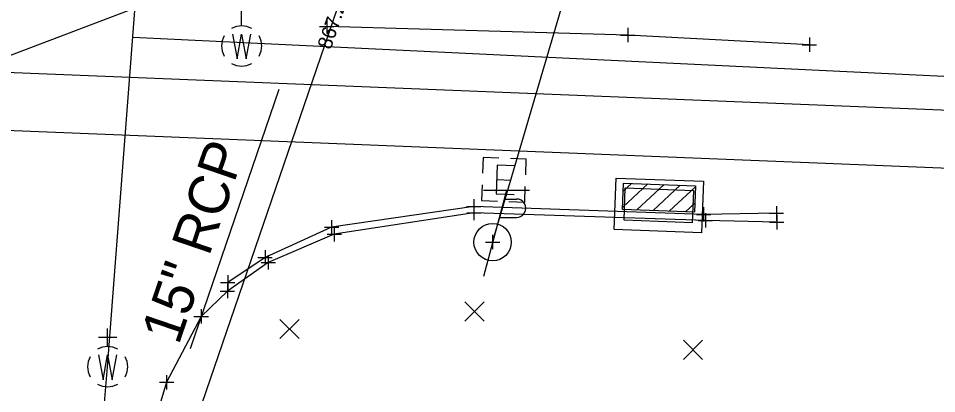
# Model space of a CAD drawing. Extents: x 1380440 to 1381945, y 468756 to 470369.
# Drawn here: x 1381624.1 to 1381687.9, y 470207.8 to 470234 of the extents above; entities that cross this region are included whole.
import ezdxf

# ---------------------------------------------------------------- set-up
doc = ezdxf.new("R2010")
doc.units = 0
for name, color, linetype in [('Animation Elements', 7, 'Continuous'), ('DR_X_Cells', 7, 'Continuous'), ('GE_P_Driveway_CL', 7, 'Continuous'), ('PM_X_Cells', 7, 'Continuous'), ('PV_P_Curb_Ramp', 7, 'Continuous'), ('PV_P_Joint', 7, 'Continuous'), ('PV_X_COP', 7, 'Continuous'), ('RW_P_Const_Limits', 7, 'Continuous'), ('RW_P_Esmt_TMP', 7, 'Continuous'), ('RW_X_CL', 7, 'Continuous'), ('SC_Scratch1', 7, 'Continuous'), ('SC_Shading1', 7, 'Continuous'), ('SH_Named_Boundary', 7, 'Continuous'), ('UT_X_Gas', 7, 'Continuous'), ('UT_X_Overhead_Combined', 7, 'Continuous'), ('UT_X_Sanitary_Line', 7, 'Continuous'), ('UT_X_Water', 7, 'Continuous'), ('X-CL', 7, 'Continuous')]:
    doc.layers.add(name, color=color, linetype=linetype)

msp = doc.modelspace()

# ---------------------------------------------------------------- linework, layer by layer
at = {"layer": 'Animation Elements'}
msp.add_lwpolyline([(1381657.035, 470218.369), (1381665.562, 470247.404)], dxfattribs=at)
at = {"layer": 'DR_X_Cells'}
msp.add_lwpolyline([(1381676.791, 470219.75), (1381671.827, 470219.886), (1381655.739, 470220.402), (1381646.018, 470218.916), (1381641.43, 470216.955), (1381638.594, 470214.962)], dxfattribs=at)
at = {"layer": 'GE_P_Driveway_CL'}
for p, q in [((1381655.103, 470212.868), (1381656.437, 470214.204)), ((1381655.103, 470214.204), (1381656.437, 470212.868)), ((1381642.237, 470211.656), (1381643.571, 470212.991)), ((1381642.237, 470212.991), (1381643.571, 470211.656)), ((1381670.301, 470210.201), (1381671.635, 470211.536)), ((1381670.301, 470211.536), (1381671.635, 470210.201))]:
    msp.add_line(p, q, dxfattribs=at)
at = {"layer": 'PM_X_Cells'}
for p, q in [((1381657.322, 470222.728), (1381658.322, 470222.691)), ((1381657.822, 470222.71), (1381657.822, 470222.71))]:
    msp.add_line(p, q, dxfattribs=at)
for points in [[(1381657.478, 470224.224), (1381656.378, 470224.264), (1381656.338, 470223.165)], [(1381659.336, 470223.054), (1381659.376, 470224.154), (1381658.277, 470224.194)], [(1381658.608, 470223.682), (1381657.359, 470223.728), (1381657.285, 470221.729), (1381658.535, 470221.683)], [(1381656.308, 470222.366), (1381656.268, 470221.266), (1381657.367, 470221.226)], [(1381658.166, 470221.196), (1381659.266, 470221.156), (1381659.306, 470222.255)]]:
    msp.add_lwpolyline(points, dxfattribs=at)
at = {"layer": 'PV_P_Curb_Ramp'}
for p, q in [((1381668.655, 470222.722), (1381668.655, 470222.722)), ((1381668.63, 470222.056), (1381668.63, 470222.056)), ((1381666.215, 470221.02), (1381666.215, 470221.02)), ((1381668.574, 470220.557), (1381668.574, 470220.557)), ((1381668.574, 470220.557), (1381668.574, 470220.557)), ((1381668.588, 470220.932), (1381668.588, 470220.932)), ((1381670.961, 470220.843), (1381670.961, 470220.843)), ((1381668.546, 470219.808), (1381668.546, 470219.808)), ((1381668.521, 470219.141), (1381668.521, 470219.141))]:
    msp.add_line(p, q, dxfattribs=at)
at = {"layer": 'PV_P_Joint'}
for p, q in [((1381667.828, 470222.419), (1381666.081, 470220.794)), ((1381666.699, 470222.461), (1381666.123, 470221.926)), ((1381668.957, 470222.377), (1381667.061, 470220.613)), ((1381670.086, 470222.335), (1381668.19, 470220.571)), ((1381671.138, 470222.222), (1381669.319, 470220.529)), ((1381671.096, 470221.089), (1381670.449, 470220.487))]:
    msp.add_line(p, q, dxfattribs=at)
for points in [[(1381671.561, 470219.027), (1381665.482, 470219.254), (1381665.615, 470222.835), (1381671.694, 470222.609)], [(1381671.072, 470220.464), (1381666.076, 470220.65), (1381666.144, 470222.482), (1381671.14, 470222.296)], [(1381670.919, 470219.719), (1381666.173, 470219.896), (1381666.256, 470222.144), (1381671.003, 470221.968)]]:
    msp.add_lwpolyline(points, close=True, dxfattribs=at)
at = {"layer": 'PV_X_COP'}
for p, q in [((1381657.998, 470221.969), (1381656.392, 470215.969)), ((1381659.598, 470221.969), (1381656.398, 470221.969)), ((1381657.838, 470221.369), (1381658.688, 470221.369)), ((1381657.497, 470220.094), (1381658.688, 470220.094))]:
    msp.add_line(p, q, dxfattribs=at)
msp.add_circle((1381657.035, 470218.369), 1.3, dxfattribs=at)
msp.add_arc((1381658.701, 470220.732), 0.638, 268.8767, 91.1233, dxfattribs=at)
at = {"layer": 'RW_P_Const_Limits'}
for p, q in [((1381639.582, 470233.429), (1381639.582, 470234.701)), ((1381639.582, 470232.029), (1381639.582, 470232.029)), ((1381630.263, 470211.092), (1381630.263, 470212.364)), ((1381630.898, 470211.729), (1381629.626, 470211.729)), ((1381630.263, 470209.692), (1381630.263, 470209.692))]:
    msp.add_line(p, q, dxfattribs=at)
for points in [[(1381638.945, 470232.849), (1381639.264, 470231.126), (1381639.582, 470232.849), (1381639.902, 470231.126), (1381640.219, 470232.849)], [(1381629.626, 470210.512), (1381629.945, 470208.789), (1381630.263, 470210.512), (1381630.583, 470208.789), (1381630.9, 470210.512)]]:
    msp.add_lwpolyline(points, dxfattribs=at)
for centre, start, end in [((1381639.582, 470232.03), 60.01836, 120.01574), ((1381639.582, 470232.03), 150.01836, 209.98164), ((1381639.582, 470232.03), 330.01836, 29.98164), ((1381639.582, 470232.03), 239.98426, 299.98164), ((1381630.263, 470209.694), 60.01836, 120.01574), ((1381630.263, 470209.694), 150.01836, 209.98164), ((1381630.263, 470209.694), 330.01836, 29.98164), ((1381630.263, 470209.694), 239.98426, 299.98164)]:
    msp.add_arc(centre, 1.4, start, end, dxfattribs=at)
at = {"layer": 'RW_P_Esmt_TMP'}
msp.add_lwpolyline([(1381676.765, 470220.385), (1381671.708, 470220.296), (1381655.718, 470220.85), (1381645.835, 470219.405), (1381641.211, 470217.307), (1381638.618, 470215.563), (1381638.594, 470214.962), (1381636.765, 470213.193), (1381634.363, 470208.616), (1381632.01, 470200.77), (1381631.562, 470195.02), (1381630.708, 470194.999), (1381628.299, 470162.981)], dxfattribs=at)
at = {"layer": 'RW_X_CL'}
msp.add_line((1381642.166, 470228.993), (1381635.993, 470210.933), dxfattribs=at)
at = {"layer": 'SC_Shading1'}
msp.add_lwpolyline([(1381679.062, 470232.112), (1381666.426, 470232.791), (1381645.502, 470233.392)], dxfattribs=at)
at = {"layer": 'SH_Named_Boundary'}
for p, q in [((1381645.502, 470233.892), (1381645.502, 470232.892)), ((1381645.002, 470233.392), (1381646.002, 470233.392)), ((1381645.502, 470233.392), (1381645.502, 470233.392)), ((1381666.426, 470233.291), (1381666.426, 470232.291)), ((1381665.926, 470232.791), (1381666.926, 470232.791)), ((1381666.426, 470232.791), (1381666.426, 470232.791)), ((1381679.062, 470232.612), (1381679.062, 470231.612)), ((1381678.562, 470232.112), (1381679.562, 470232.112)), ((1381679.062, 470232.112), (1381679.062, 470232.112)), ((1381655.718, 470221.35), (1381655.718, 470220.35)), ((1381655.718, 470221.35), (1381655.718, 470220.35)), ((1381655.218, 470220.85), (1381656.218, 470220.85)), ((1381655.218, 470220.85), (1381656.218, 470220.85)), ((1381655.239, 470220.402), (1381656.239, 470220.402)), ((1381655.239, 470220.402), (1381656.239, 470220.402)), ((1381655.718, 470220.85), (1381655.718, 470220.85)), ((1381655.718, 470220.85), (1381655.718, 470220.85)), ((1381655.739, 470220.902), (1381655.739, 470219.902)), ((1381655.739, 470220.902), (1381655.739, 470219.902)), ((1381655.739, 470220.402), (1381655.739, 470220.402)), ((1381655.739, 470220.402), (1381655.739, 470220.402)), ((1381671.708, 470220.796), (1381671.708, 470219.796)), ((1381671.827, 470220.386), (1381671.827, 470219.386)), ((1381676.265, 470220.385), (1381677.265, 470220.385)), ((1381676.765, 470220.885), (1381676.765, 470219.885)), ((1381676.765, 470220.385), (1381676.765, 470220.385)), ((1381645.835, 470219.905), (1381645.835, 470218.905)), ((1381671.208, 470220.296), (1381672.208, 470220.296)), ((1381671.327, 470219.886), (1381672.327, 470219.886)), ((1381671.708, 470220.296), (1381671.708, 470220.296)), ((1381671.827, 470219.886), (1381671.827, 470219.886)), ((1381676.291, 470219.75), (1381677.291, 470219.75)), ((1381676.791, 470220.25), (1381676.791, 470219.25)), ((1381676.791, 470219.75), (1381676.791, 470219.75)), ((1381645.335, 470219.405), (1381646.335, 470219.405)), ((1381645.835, 470219.405), (1381645.835, 470219.405)), ((1381646.018, 470219.416), (1381646.018, 470218.416)), ((1381645.518, 470218.916), (1381646.518, 470218.916)), ((1381646.018, 470218.916), (1381646.018, 470218.916)), ((1381657.035, 470218.869), (1381657.035, 470217.869)), ((1381657.035, 470218.869), (1381657.035, 470217.869)), ((1381641.211, 470217.807), (1381641.211, 470216.807)), ((1381641.211, 470217.807), (1381641.211, 470216.807)), ((1381656.535, 470218.369), (1381657.535, 470218.369)), ((1381656.535, 470218.369), (1381657.535, 470218.369)), ((1381657.035, 470218.369), (1381657.035, 470218.369)), ((1381657.035, 470218.369), (1381657.035, 470218.369)), ((1381640.711, 470217.307), (1381641.711, 470217.307)), ((1381640.711, 470217.307), (1381641.711, 470217.307)), ((1381641.211, 470217.307), (1381641.211, 470217.307)), ((1381641.211, 470217.307), (1381641.211, 470217.307)), ((1381641.43, 470217.455), (1381641.43, 470216.455)), ((1381641.43, 470217.455), (1381641.43, 470216.455)), ((1381640.93, 470216.955), (1381641.93, 470216.955)), ((1381640.93, 470216.955), (1381641.93, 470216.955)), ((1381641.43, 470216.955), (1381641.43, 470216.955)), ((1381641.43, 470216.955), (1381641.43, 470216.955)), ((1381638.618, 470216.063), (1381638.618, 470215.063)), ((1381638.118, 470215.563), (1381639.118, 470215.563)), ((1381638.594, 470215.462), (1381638.594, 470214.462)), ((1381638.594, 470215.462), (1381638.594, 470214.462)), ((1381638.618, 470215.563), (1381638.618, 470215.563)), ((1381638.094, 470214.962), (1381639.094, 470214.962)), ((1381638.094, 470214.962), (1381639.094, 470214.962)), ((1381638.594, 470214.962), (1381638.594, 470214.962)), ((1381638.594, 470214.962), (1381638.594, 470214.962)), ((1381636.765, 470213.693), (1381636.765, 470212.693)), ((1381636.765, 470213.693), (1381636.765, 470212.693)), ((1381636.265, 470213.193), (1381637.265, 470213.193)), ((1381636.265, 470213.193), (1381637.265, 470213.193)), ((1381636.765, 470213.193), (1381636.765, 470213.193)), ((1381636.765, 470213.193), (1381636.765, 470213.193)), ((1381634.363, 470209.116), (1381634.363, 470208.116)), ((1381633.863, 470208.616), (1381634.863, 470208.616)), ((1381634.363, 470208.616), (1381634.363, 470208.616))]:
    msp.add_line(p, q, dxfattribs=at)
at = {"layer": 'UT_X_Gas'}
msp.add_line((1381720.282, 470226.259), (1381596.732, 470231.245), dxfattribs=at)
at = {"layer": 'UT_X_Overhead_Combined'}
msp.add_lwpolyline([(1381540.8, 469054.263), (1381515.279, 469203.101), (1381529.165, 469390.12), (1381543.86, 469565.781), (1381559.775, 469757.408), (1381571.968, 469887.64), (1381581.264, 470018.199), (1381595.795, 470220.833), (1381665.562, 470247.404)], dxfattribs=at)
at = {"layer": 'UT_X_Sanitary_Line'}
msp.add_line((1381906.161, 470214.727), (1381603.055, 470226.96), dxfattribs=at)
at = {"layer": 'UT_X_Water'}
for p, q in [((1381630.263, 470209.692), (1381638.864, 470321.963)), ((1381710.245, 470228.843), (1381632.019, 470232.609)), ((1381545.409, 469194.714), (1381630.263, 470209.692))]:
    msp.add_line(p, q, dxfattribs=at)
at = {"layer": 'X-CL'}
msp.add_line((1381633.903, 470198.558), (1381646.794, 470236.273), dxfattribs=at)

# ---------------------------------------------------------------- texts
at = {"layer": 'RW_X_CL'}
msp.add_text('15" RCP', height=2.8, rotation=71.12967, dxfattribs=at).set_placement((1381635.194, 470211.143))
at = {"layer": 'SC_Scratch1'}
msp.add_text("867.24'", height=1, rotation=71.12967, dxfattribs=at).set_placement((1381645.769, 470231.728))

doc.saveas('drawing.dxf')
